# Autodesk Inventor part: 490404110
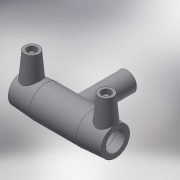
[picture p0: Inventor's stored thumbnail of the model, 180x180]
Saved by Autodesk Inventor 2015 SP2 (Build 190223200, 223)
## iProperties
Created: 2017-06
Part Number: 490404110
Material: Generic
Description: PLASSON TEE 110-110-110
Document SubType Name: Modeling
Designer: KIM
Mass: 57.3761 g
Surface Area: 241.06 cm^2
Volume: 57.3761 cm^3
Density: 1 g/cm^3
Appearance: Default
Author: KIM
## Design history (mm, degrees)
derived "490404.ipt"
feature "Solid1::490404.ipt"
tag "TaggingFeature1"
body "Solid1"
other parameters: "d0" = 326, "d2" = 143, "d3" = 71, "d4" = 81.5, "d5" = 128.7, "d6" = 104.5, "d8" = 168 deg, "d10" = 28.4, "d11" = 9.46667, "d13" = 326, "d14" = 17.6296, "d17" = 99, "d19" = 3.52592, "d20" = 168 deg, "d22" = 132.99, "d23" = 143, "d24" = 129.0003, "d25" = 135 deg, "d26" = 228.2, "d27" = 135 deg, "d29" = 81, "d30" = 15, "d31" = 130.4, "d34" = 5 deg, "d35" = 15, "d39" = 5 deg, "d40" = 9.6, "d41" = 4.8, "d42" = 6, "d43" = 0, "d45" = 4, "d46" = 14, "d47" = 0, "d51" = 0, "d52" = 88, "d54" = 0, "d55" = 128.7, "d56" = 143, "d57" = 114.1, "d58" = 135 deg, "d59" = 71, "d60" = 71, "d61" = 135 deg, "d72" = 148.33, "d73" = 74.165, "d75" = 115.5, "d77" = 0, "d78" = 88, "d80" = 0, "d82" = 88.5, "d83" = 0, "d84" = 3, "d85" = 0, "d86" = 3, "d87" = 0, "d88" = 20.59, "d89" = 5.1475, "d90" = 20.59, "L_" = 326, "L_1" = 71, "D_" = 143, "A_" = 81, "d_2" = 12
